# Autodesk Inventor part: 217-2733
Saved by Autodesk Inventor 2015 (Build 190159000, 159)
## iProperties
Created: 2014-11
Part Number: 217-2733
Material: Generic
Document SubType Name: Modeling
Designer: User
Density: 1 g/cm^3
Appearance: Default
Author: User
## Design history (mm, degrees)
node "217-2733.ipt1"
node "Revolve1"
node "Base1"
